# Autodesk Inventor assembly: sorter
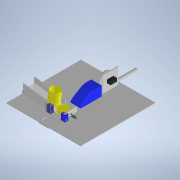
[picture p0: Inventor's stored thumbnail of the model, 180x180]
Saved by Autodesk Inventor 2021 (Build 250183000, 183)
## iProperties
Created: 2026-10
Part Number: sorter
Document SubType Name: Assembly
Designer: alolo
Author: alolo
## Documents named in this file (12)
- C:\Users\alolo\Documents\Inventor\Design 1\sorter.iam
- C:\Users\alolo\Documents\Inventor\Design 1\base.ipt
- C:\Users\alolo\Documents\Inventor\Design 1\centering.iam
- C:\Users\alolo\Documents\Inventor\Design 1\color_sensor_holder.iam
- C:\Users\alolo\Documents\Inventor\Design 1\laser_assembly.iam
- C:\Users\alolo\Documents\Inventor\Design 1\laser_detector.iam
- C:\Users\alolo\Documents\Inventor\Design 1\pusher.iam
- C:\Users\alolo\Documents\Inventor\Design 1\slide.iam
- C:\Users\alolo\Documents\Inventor\Design 1\yellow_base.ipt
- C:\Users\alolo\Documents\Inventor\Design 1\yellow_lid.ipt
- C:\Users\alolo\Documents\Inventor\Design 1\IR_LM393_pin.ipt
- C:\Users\alolo\Documents\Inventor\Design 1\reciever_wall.ipt
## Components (12 placed, 11 different names)
1. base:1 — Mate:4, Mate:6, Mate:11, Mate:12, Mate:20, Mate:23, Mate:24, Mate:26, Mate:30
2. centering:1 [sub-assembly] — Mate:20, Mate:21, Mate:27, Mate:29
3. color_sensor_holder:1 [sub-assembly] — Mate:4, Mate:9, Mate:10, Mate:17, Mate:21, Mate:25, Mate:27, Mate:35, Mate:36, Mate:38
4. laser_assembly:1 [sub-assembly] — Mate:11, Mate:30, Mate:31, Flush:1, Mate:33
5. laser_detector:1 [sub-assembly] — Mate:12, Mate:32, Mate:33
6. slide:1 [sub-assembly] — Mate:6, Mate:7, Mate:9, Mate:10, Mate:16, Mate:31
7. yellow_base:1 — Mate:16
8. yellow_lid:1 — Mate:17
9. pusher:1 [sub-assembly] — Mate:23, Mate:24, Mate:25, Mate:26, Mate:28
10. base:2 — Mate:28, Mate:29, Mate:32, Mate:34, Mate:37
11. IR_LM393_pin:1 — Mate:34, Mate:35, Mate:36, Mate:41
12. reciever_wall:1 — Mate:37, Mate:38, Mate:39, Mate:40
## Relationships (31: Mate 30, Flush 1)
- Mate:4: base:1 ↔ color_sensor_holder:1
- Mate:6: base:1 ↔ slide:1
- Mate:7: slide:1
- Mate:9: color_sensor_holder:1 ↔ slide:1
- Mate:10: color_sensor_holder:1 ↔ slide:1
- Mate:11: base:1 ↔ laser_assembly:1
- Mate:12: base:1 ↔ laser_detector:1
- Mate:16: slide:1 ↔ yellow_base:1
- Mate:17: color_sensor_holder:1 ↔ yellow_lid:1
- Mate:20: base:1 ↔ centering:1
- Mate:21: centering:1 ↔ color_sensor_holder:1
- Mate:23: base:1 ↔ pusher:1
- Mate:24: base:1 ↔ pusher:1
- Mate:25: color_sensor_holder:1 ↔ pusher:1
- Mate:26: base:1 ↔ pusher:1
- Mate:27: centering:1 ↔ color_sensor_holder:1
- Mate:28: pusher:1 ↔ base:2
- Mate:29: centering:1 ↔ base:2
- Mate:30: base:1 ↔ laser_assembly:1
- Mate:31: laser_assembly:1 ↔ slide:1
- Flush:1: laser_assembly:1
- Mate:32: laser_detector:1 ↔ base:2
- Mate:33: laser_assembly:1 ↔ laser_detector:1
- Mate:34: base:2 ↔ IR_LM393_pin:1
- Mate:35: color_sensor_holder:1 ↔ IR_LM393_pin:1
- Mate:36: color_sensor_holder:1 ↔ IR_LM393_pin:1
- Mate:37: base:2 ↔ reciever_wall:1
- Mate:38: color_sensor_holder:1 ↔ reciever_wall:1
- Mate:39: reciever_wall:1
- Mate:40: reciever_wall:1
- Mate:41: IR_LM393_pin:1
